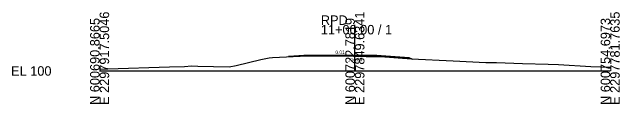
# Model space of a CAD drawing. Extents: x -313 to 385, y -480 to 1023.
# Drawn here: x -25.7 to 152.8, y 490.3 to 517.3 of the extents above; entities that cross this region are included whole.
import ezdxf

# ---------------------------------------------------------------- set-up
doc = ezdxf.new("R2010")
doc.units = 0
for name, color, linetype in [('Exist Cross Section Cell', 7, 'Continuous'), ('Exist XS Center Line Elevation Label', 7, 'Continuous'), ('Exist XS Ground Line', 7, 'Continuous'), ('Prop CMT Pvmt Surface', 7, 'Continuous'), ('Prop CMT Pvmt Surface Overlay', 7, 'Continuous'), ('Prop CMT Shld Paved Course 1', 7, 'Continuous'), ('Prop CMT Slope Grass', 7, 'Continuous'), ('Prop XS Earthwork Shape', 7, 'Continuous'), ('Prop XS SE Text', 7, 'Continuous')]:
    doc.layers.add(name, color=color, linetype=linetype)

msp = doc.modelspace()

# ---------------------------------------------------------------- linework, layer by layer
at = {"layer": 'Exist Cross Section Cell'}
for p, q in [((75, 500), (75, 513.56)), ((0, 500), (75, 500)), ((75, 500), (150, 500))]:
    msp.add_line(p, q, dxfattribs=at)
at = {"layer": 'Exist XS Ground Line'}
msp.add_lwpolyline([(0, 500.54), (2.39, 500.65), (20.55, 501.23), (24.92, 501.36), (26.96, 501.48), (28.87, 501.37), (38.04, 501.22), (40.13, 501.61), (47.41, 503.34), (49.83, 503.9), (50.81, 503.98), (60.97, 504.49), (61.73, 504.52), (63.13, 504.48), (63.55, 504.47), (64.4, 504.46), (66.31, 504.45), (68.46, 504.43), (69.07, 504.42), (69.61, 504.42), (71.83, 504.41), (72.63, 504.41), (74.6, 504.37), (75, 504.36), (76.39, 504.32), (77.36, 504.31), (78.27, 504.3), (80.28, 504.28), (81.61, 504.27), (82.51, 504.21), (91.63, 503.53), (103.83, 503.02), (113.48, 502.53), (116.62, 502.48), (124.21, 502.24), (131.75, 501.96), (134.77, 501.89), (144.35, 501.34), (150, 501.07)], dxfattribs=at)
at = {"layer": 'Prop CMT Pvmt Surface'}
for p, q in [((81.61, 504.35), (59.81, 504.33)), ((81.36, 504.6), (60.06, 504.58))]:
    msp.add_line(p, q, dxfattribs=at)
msp.add_lwpolyline([(60.06, 504.58), (59.81, 504.33)], dxfattribs=at)
at = {"layer": 'Prop CMT Pvmt Surface Overlay'}
for p, q in [((81.61, 504.35), (59.81, 504.33)), ((81.36, 504.6), (60.06, 504.58))]:
    msp.add_line(p, q, dxfattribs=at)
at = {"layer": 'Prop CMT Shld Paved Course 1'}
for points in [[(60.06, 504.58), (59.81, 504.33)], [(81.61, 504.35), (81.36, 504.6)]]:
    msp.add_lwpolyline(points, dxfattribs=at)
at = {"layer": 'Prop CMT Slope Grass'}
for p, q in [((60.06, 504.58), (55.53, 504.22)), ((60.06, 504.58), (59.91, 504.44)), ((81.36, 504.6), (90.93, 503.83)), ((81.36, 504.6), (81.7, 504.26)), ((90.93, 503.83), (91.86, 503.52))]:
    msp.add_line(p, q, dxfattribs=at)
at = {"layer": 'Prop XS Earthwork Shape'}
for points in [[(55.53, 504.22), (59.91, 504.44), (60.06, 504.58)], [(91.63, 503.53), (91.86, 503.52), (90.93, 503.83), (81.36, 504.6), (81.7, 504.26), (82.51, 504.21)]]:
    msp.add_lwpolyline(points, close=True, dxfattribs=at)

# ---------------------------------------------------------------- texts
at = {"layer": 'Exist Cross Section Cell'}
for s, p in [('E 2297917.5046', (2.8, 490)), ('E 2297849.6341', (77.8, 490)), ('E 2297781.7635', (152.8, 490)), ('N 600690.8665', (0, 490)), ('N 600722.7819', (75, 490)), ('N 600754.6973', (150, 490))]:
    msp.add_text(s, height=2.8, rotation=90, dxfattribs=at).set_placement(p)
for s, p in [('RPD', (65, 513.56)), ('11+00.00 / 1', (65, 510.76)), ('EL 100', (-26, 498.6))]:
    msp.add_text(s, height=2.8, dxfattribs=at).set_placement(p)
at = {"layer": 'Exist XS Center Line Elevation Label'}
msp.add_text('104.36', height=1, dxfattribs=at).set_placement((72.9, 502.86))
at = {"layer": 'Prop XS SE Text'}
msp.add_text('0.01', height=1, rotation=0.8783, dxfattribs=at).set_placement((69.3, 505))

doc.saveas('drawing.dxf')
